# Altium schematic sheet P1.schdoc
size 297 x 209 mm; Symbol: Drawing-Symbol_A4; @Project Name: fmcw; @Page Count: 1; @Update Date: 2026-07-30; @Create Date: 2026-07-30; @Schematic Name: Schematic2; @Page No: 1; @Page Name: P1; Company: EasyEDA.com; Version: V1.0; Page Size: A4; Device: Drawing-Symbol_A4; @Create Time: 16:14:03; @Update Time: 16:14:03; Border: 1; Width: 1170; Height: 825; Region Start: 1; X Region Count: 6; Y Region Count: 4; Blade Width: 10; Title Block Position: 3; @Board Name: PCB2
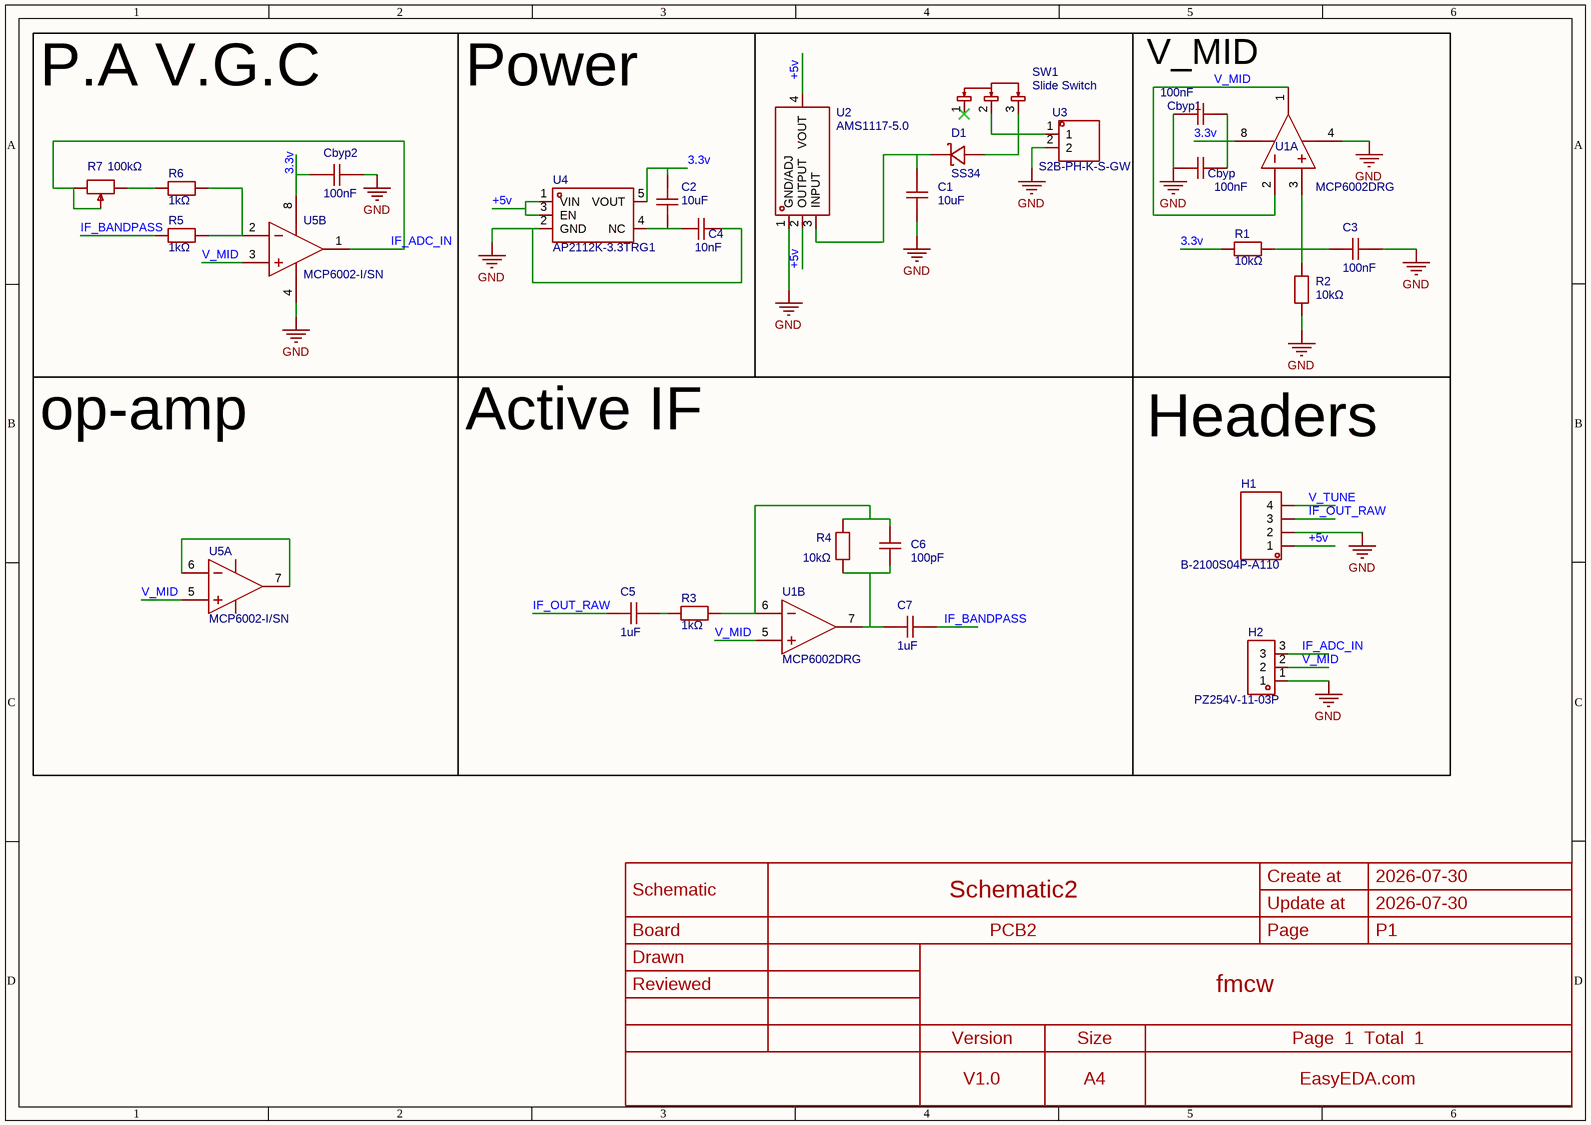
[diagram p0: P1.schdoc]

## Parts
C1  10uF  [C0603]
C2  10uF  [C0603]
C3  100nF  [C0402]
C4  10nF  [C0402]
C5  1uF  [C0402]
C6  100pF  [C0603]
C7  1uF  [C0402]
Cbyp  100nF  [C0402]
Cbyp1  100nF  [C0402]
Cbyp2  100nF  [C0402]
D1  SS34  [SMA_L4.3-W2.6-LS5.2-RD]
H1  B-2100S04P-A110  [HDR-TH_4P-P2.54-V-M]
H2  PZ254V-11-03P  [HDR-TH_3P-P2.54-V-M_PZ254V-11-03P]
R1  10kΩ  [R0402]
R2  10kΩ  [R0402]
R3  1kΩ  [R0402]
R4  10kΩ  [R0402]
R5  1kΩ  [R0402]
R6  1kΩ  [R0402]
R7  100kΩ  [RES-ADJ-TH_3296W]
SW1  Slide Switch  [SW-SMD_MST-12D18G4-SPDT-SLIDE-SWITCH]
U1  MCP6002DRG  [SOP-8_L4.9-W3.9-P1.27-LS6.0-BL]  (parts A,B of 2)
U2  AMS1117-5.0  [SOT-223-3_L6.5-W3.4-P2.30-LS7.0-BR]
U3  S2B-PH-K-S-GW  [CONN-TH_S2B-PH-K-S-GW]
U4  AP2112K-3.3TRG1  [SOT-23-5_L2.9-W1.6-P0.95-LS2.8-BR]
U5  MCP6002-I/SN  [SOIC-8_L4.9-W3.9-P1.27-LS6.0-BL]  (parts A,B of 2)

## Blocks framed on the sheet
P.A V.G.C: Cbyp2 R5-R7 U5
Power: C1-C4 Cbyp Cbyp1 D1 R1 R2 SW1 U1-U4
op-amp: U5
Active IF: C5-C7 R3 R4 U1
Headers: H1 H2

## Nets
GND: C1.1 C3.2 C4.2 Cbyp.2 Cbyp1.2 Cbyp2.2 H1.2 H2.1 R2.1 U1.4(VSS) U2.1(GND/ADJ) U3.2 U4.2(GND) U5.4(VSS)
3.3v: C2.1 Cbyp.1 Cbyp1.1 Cbyp2.1 R1.1 U1.8(VDD) U4.5(VOUT) U5.8(VDD)
+5v: H1.1 U2.2(OUTPUT) U2.4(VOUT) U4.1(VIN) U4.3(EN)
IF_ADC_IN: H2.3 R7.1 R7.2 U5.1(VOUTA)
IF_BANDPASS: C7.1 R5.1
IF_OUT_RAW: C5.2 H1.3
V_MID: H2.2 U1.1(OUTA) U1.2(INA-) U1.5(INB+) U5.3(VINA+) U5.5(VINB+)
V_TUNE: H1.4
NetC1_2: C1.2 D1.1(K) U2.3(INPUT)
NetC2_2: C2.2 C4.1 U4.4(NC)
NetC3_1: C3.1 R1.2 R2.2 U1.3(INA+)
NetC5_1: C5.1 R3.1
NetC6_1: C6.1 C7.2 R4.2 U1.7(OUTB)
NetC6_2: C6.2 R3.2 R4.1 U1.6(INB-)
NetD1_2: D1.2(A) SW1.3
NetR5_2: R5.2 R6.2 U5.2(VINA-)
NetR6_1: R6.1 R7.3
NetSW1_2: SW1.2 U3.1
NetU5_6: U5.6(VINB-) U5.7(VOUTB)

Not connected (* = marked no-connect by the designer): SW1 1*

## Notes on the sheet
- V_MID

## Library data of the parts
C1 C2 = CL10A106KP8NNNC: Capacitance:10uF Tolerance:±10% Tolerance:±10% Voltage Rating:10V Temperature Coefficient:X5R; Manufacturer: SAMSUNG(三星); AddInBom: yes; ModelId: 624118aa3cc7497086c383c2d72e08520819f05c4eef4c71ace90d822a990e87; ModelName: C0603_L1.6-W0.8-H0.8; ModelTransform: 62.992,31.496,0,0,0,0,0,0,0; Tolerance: ±10%; Voltage Rating: 10V; Temperature Coefficient: X5R
C3 = CL05B104KO5NNNC: Capacitance:100nF Tolerance:±10% Tolerance:±10% Voltage Rating:16V Temperature Coefficient:X7R; Manufacturer: SAMSUNG(三星); AddInBom: yes; ModelId: b7d13df3e9464d7a99d0651d1a5b4d570819f05c4eef4c71ace90d822a990e87; ModelName: C0402_L1.0-W0.5-H0.5; ModelTransform: 39.37,19.685,0,0,0,0,0,0,0; Tolerance: ±10%; Voltage Rating: 16V; Temperature Coefficient: X7R
C4 = CL05B103KB5NNNC: Capacitance:10nF Tolerance:±10% Tolerance:±10% Voltage Rating:50V Temperature Coefficient:X7R; Manufacturer: SAMSUNG(三星); AddInBom: yes; ModelId: b7d13df3e9464d7a99d0651d1a5b4d570819f05c4eef4c71ace90d822a990e87; ModelName: C0402_L1.0-W0.5-H0.5; ModelTransform: 39.37,19.685,0,0,0,0,0,0,0; Tolerance: ±10%; Voltage Rating: 50V; Temperature Coefficient: X7R
C5 C7 = TCC0402X5R105M6R3AT: Capacitance:1uF Tolerance:±20% Tolerance:±20% Voltage Rating:6.3V Temperature Coefficient:X5R; Manufacturer: CCTC(三环); 3D Model: b7d13df3e9464d7a99d0651d1a5b4d570819f05c4eef4c71ace90d822a990e87; 3D Model Transform: 39.37,19.685,0,0,0,0,0,0,0; Tolerance: ±20%; Voltage Rating: 6.3V; Temperature Coefficient: X5R; AddInBom: yes; ModelName: C0402_L1.0-W0.5-H0.5
C6 = CL10C101JB8NNNC: Capacitance:100pF Tolerance:±5% Tolerance:±5% Voltage Rating:50V Temperature Coefficient:C0G; Manufacturer: SAMSUNG(三星); AddInBom: yes; ModelId: 624118aa3cc7497086c383c2d72e08520819f05c4eef4c71ace90d822a990e87; ModelName: C0603_L1.6-W0.8-H0.8; ModelTransform: 62.992,31.496,0,0,0,0,0,0,0; Tolerance: ±5%; Voltage Rating: 50V; Temperature Coefficient: C0G
Cbyp Cbyp1 Cbyp2 = CL05B104KO5NNNC: Capacitance:100nF Tolerance:±10% Tolerance:±10% Voltage Rating:16V Temperature Coefficient:X7R; Manufacturer: SAMSUNG(三星); 3D Model: b7d13df3e9464d7a99d0651d1a5b4d570819f05c4eef4c71ace90d822a990e87; 3D Model Transform: 39.37,19.685,0,0,0,0,0,0,0; Tolerance: ±10%; Voltage Rating: 16V; Temperature Coefficient: X7R; AddInBom: yes; ModelName: C0402_L1.0-W0.5-H0.5
D1 = SS34_C8678: Diode Configuration:Independent Voltage - Forward(Vf@If):550mV@3A Voltage - DC Reverse(Vr):40V Current - Rectified:3A Reverse Leakage Current (Ir):500uA@40V Operating Junction Temperature Range:-55℃~+125℃ Operating Junction Temperature Range:-55℃~+125℃; Manufacturer: MDD(辰达半导体); AddInBom: yes; ModelId: e3551acb3c5a4975a5e9d36087fe1fa20819f05c4eef4c71ace90d822a990e87; ModelTransform: 185.039,102.362,0,0,0,0,0,0,0; Voltage - DC Reverse(Vr): 40V; Current - Rectified: 3A
H1 = B-2100S04P-A110: Pin Structure:1x4P Pitch:2.54mm Row Spacing:- Circluar Pins/Square Pins:Pin Header Mounting Type:Through Hole Number of Rows:1 Number of Pins:4P Current Rating:3A Voltage Rating (Max):- Length of Mating Pin:6mm Insulation Height:2.54mm Length of End Conne; Manufacturer: Ckmtw(灿科盟); Symbol: Header-Male-2.54_1x4; AddInBom: yes; ModelId: 69e0934d9b9245f6ab499bc5a319b3aa0819f05c4eef4c71ace90d822a990e87; ModelName: HDR-TH_4P-P2.54-M-LI-1X4P; ModelTransform: 399.999,104.7242,0,0,0,0,0,0,-118.11; Pin Structure: 1x4P; Pitch: 2.54mm; Current Rating: 3A
H2 = PZ254V-11-03P: Pin Structure:1x3P Pitch:2.54mm Row Spacing:- Circluar Pins/Square Pins:Pin Header Mounting Type:Through Hole Number of Rows:1 Number of Pins:3P Current Rating:3A Voltage Rating (Max):250V Length of Mating Pin:6mm Insulation Height:2.5mm Length of End Con; Manufacturer: XFCN(兴飞); Symbol: PZ254V-11-03P_C2937625; AddInBom: yes; ModelId: bd28a638fbd247be9398fd5d39c366ec0819f05c4eef4c71ace90d822a990e87; ModelTransform: 300.3931,100,0,0,0,0,0,0,-118.11; Pin Structure: 1x3P; Pitch: 2.54mm; Current Rating: 3A; Voltage Rating (Max): 250V
R1 R2 = FRC0402F1002TS: Type:Thick Film Resistor Resistance:10kΩ Tolerance:±1% Tolerance:±1% Power(Watts):62.5mW Voltage-Supply(Max):50V Temperature Coefficient:±100ppm/℃ Temperature Coefficient:±100ppm/℃ Operating Temperature:-55℃~+155℃ Operating Temperature:-55℃~+155℃; Manufacturer: FOJAN(富捷); AddInBom: yes; ModelId: efdecb7dae4442949d28eecaf748420f0819f05c4eef4c71ace90d822a990e87; ModelName: R0402_L1.0-W0.5-H0.4; ModelTransform: 39.37,19.685,0,0,0,0,0,0,0; Tolerance: ±1%; Power(Watts): 62.5mW; Voltage-Supply(Max): 50V
R3 R5 R6 = FRC0402J102 TS: Type:Thick Film Resistor Resistance:1kΩ Tolerance:±5% Tolerance:±5% Power(Watts):62.5mW Voltage-Supply(Max):50V Temperature Coefficient:±100ppm/℃ Temperature Coefficient:±100ppm/℃ Operating Temperature:-55℃~+155℃ Operating Temperature:-55℃~+155℃; Manufacturer: FOJAN(富捷); 3D Model: efdecb7dae4442949d28eecaf748420f0819f05c4eef4c71ace90d822a990e87; 3D Model Transform: 39.37,19.685,0,0,0,0,0,0,0; Tolerance: ±5%; Power(Watts): 62.5mW; Voltage-Supply(Max): 50V; AddInBom: yes; ModelName: R0402_L1.0-W0.5-H0.4
R4 = FRC0402F1002TS: Type:Thick Film Resistor Resistance:10kΩ Tolerance:±1% Tolerance:±1% Power(Watts):62.5mW Voltage-Supply(Max):50V Temperature Coefficient:±100ppm/℃ Temperature Coefficient:±100ppm/℃ Operating Temperature:-55℃~+155℃ Operating Temperature:-55℃~+155℃; Manufacturer: FOJAN(富捷); 3D Model: efdecb7dae4442949d28eecaf748420f0819f05c4eef4c71ace90d822a990e87; 3D Model Transform: 39.37,19.685,0,0,0,0,0,0,0; Tolerance: ±1%; Power(Watts): 62.5mW; Voltage-Supply(Max): 50V; AddInBom: yes; ModelName: R0402_L1.0-W0.5-H0.4
R7 = 3296W-1-104LF: Resistance:100kΩ Tolerance:±10% Tolerance:±10% Power(Watts):500mW Temperature Coefficient:±100ppm/℃ Temperature Coefficient:±100ppm/℃ Number of Turns:; Manufacturer: BOURNS; AddInBom: yes; ModelId: d75c81813a0c4fc5896bd8a59ffd69dd0819f05c4eef4c71ace90d822a990e87; ModelTransform: 374.015,188.976,0,90,0,0,2.362,0.005,-137.795; Tolerance: ±10%; Power(Watts): 500mW
SW1 = MST-12D18G4 SPDT Slide Switch: Circuit:SPDT Actuator Style:Rectangular Columnar Termination Style:SMD(SMT) Tab Length:9.1mm Width:3.5mm Switch Height:7.5mm Mounting Type:Surface Mount, Right Angle Actuator Color:Black Current Rating:100mA Voltage Rating:12V Life:10,000 Cycles Operating; Manufacturer: SHOU HAN(首韩); AddInBom: yes; ModelId: 054f6ac983204f28b99156bbc43be73a0819f05c4eef4c71ace90d822a990e87; ModelTransform: 358.661,381.889,0,0,0,0,0,-161.417,-19.685; Circuit: SPDT; Switch Height: 7.5mm; Actuator Color: Black; Current Rating: 100mA; Voltage Rating: 12V
U1 = MCP6002DRG: Number of Channels:2 Maximum Power Supply Range (Vdd-Vss):7.5V Rail to Rail:Rail-to-Rail Input, Rail-to-Rail Output Gain Bandwidth Product:1MHz Vos - Input Offset Voltage:3.5mV Input Offset Voltage Drift(Vos TC):2.7uV/℃ Slew Rate:800V/ms Ib - Input Bias C; Manufacturer: HGC(深圳汉芯); Relevance: []; AddInBom: yes; ModelId: 9e479aa4755a4392b89c401224ad12750819f05c4eef4c71ace90d822a990e87; ModelName: SOP-8_L4.9-W3.9-P1.27-LS6.0-BL-1; ModelTransform: 192.913,236.22,0,0,0,0,-0.393,2.749,0; Number of Channels: 2; Maximum Power Supply Range (Vdd-Vss): 7.5V; Gain Bandwidth Product: 1MHz; Vos - Input Offset Voltage: 3.5mV; Ib - Input Bias Current: 1pA; Input Voltage Noise Density: 27nV/√Hz@1kHz; Common Mode Rejection Ratio(CMRR): 70dB; Quiescent Current: 75uA; Output Current: 84mA; Single supply: 1.8V~6V
U2 = AMS1117-5.0_C18212701: Output Type:Fixed Voltage - Supply:12V Output Voltage:5V Output Voltage:5V Output Current:1A Power Supply Rejection Ratio (PSRR):- Voltage Dropout:1.3V@(1A) standby current:4mA Noise:- Features:Over Current Protection；Thermal Shutdown Operating Temperatur; Manufacturer: TECH PUBLIC(台舟); AddInBom: yes; ModelId: e5f8b32b785646b6abbef6d5ae2fe0600819f05c4eef4c71ace90d822a990e87; ModelName: SOT-223-4P_L6.5-W3.5-H1.6-LS7.0-P2.30; ModelTransform: 279.89794,255.905,0,180,0,0,-3.9385,-0.0005,0; Output Type: Fixed; Voltage - Supply: 12V; Output Voltage: 5V; standby current: 4mA; Output Configuration: Positive; Number of Outputs: 1
U3 = S2B-PH-K-S-GW: Pins Structure:1x2P Pitch:2mm Mounting Type:Right Angle Reference Series:PH Number of Pins:2P Number of Rows:1 Number of PINs Per Row:2 Row Spacing:- Current Rating:2A Contact Material:Brass Contact Plating:Tin Operating Temperature:-25℃~+85℃ Operating Te; Manufacturer: JST; AddInBom: yes; ModelId: 1dc56e0a126b488da226fc64d36e59340819f05c4eef4c71ace90d822a990e87; ModelTransform: 232.283,299.212,0,0,0,0,0,97.047,-133.858; Pins Structure: 1x2P; Pitch: 2mm; Reference Series: PH; Number of PINs Per Row: 2; Current Rating: 2A; Voltage Rating: 100V; Plastic Material: PA66; Flame Retardant Rating: UL94V-0; Supplementary Features: K Pin; Z-Height of the Board: 4.8mm; X-Length of Bottom Edge on Board (Spacing Line): 5.9mm; Y-Width of Bottom Edge on Board: 7.6mm
U4 = AP2112K-3.3TRG1_C23380830: Output Configuration:Positive Voltage - Supply:5.5V Output Voltage:3.3V Output Voltage:3.3V Output Current:600mA Power Supply Rejection Ratio (PSRR):75dB@(1kHz) Voltage Dropout:320mV@(600mA) standby current:10uA Noise:- Features:Enable control；Over Curren; Manufacturer: TECH PUBLIC(台舟); AddInBom: yes; ModelId: 5bf53fa97d9848eeb37d584d4730b7f10819f05c4eef4c71ace90d822a990e87; ModelTransform: 114.173,114.173,0,90,0,0,0,0,0; Voltage - Supply: 5.5V; Output Voltage: 3.3V; standby current: 10uA; Output Type: Fixed; Number of Outputs: 1
U5 = MCP6002-I/SN: Number of Channels:2 Maximum Power Supply Range (Vdd-Vss):5.5V Rail to Rail:Rail-to-Rail Input, Rail-to-Rail Output Gain Bandwidth Product:1MHz Vos - Input Offset Voltage:4.5mV Input Offset Voltage Drift(Vos TC):2uV/℃ Slew Rate:600V/ms Ib - Input Bias Cur; Manufacturer: MICROCHIP(美国微芯); Relevance: []; AddInBom: yes; ModelId: 2ec1ac1bf9bf4d09a988fcee15e6a02d0819f05c4eef4c71ace90d822a990e87; ModelName: SOIC-8_L4.9-W3.9-H1.7-LS6.0-P1.27; ModelTransform: 192.913,236.22,0,0,0,0,0,0,0; Number of Channels: 2; Maximum Power Supply Range (Vdd-Vss): 5.5V; Gain Bandwidth Product: 1MHz; Vos - Input Offset Voltage: 4.5mV; Input Offset Voltage Drift(Vos TC): 2uV/℃; Ib - Input Bias Current: 1pA; Input Voltage Noise Density: 28nV/√Hz@1kHz; Common Mode Rejection Ratio(CMRR): 76dB; Quiescent Current: 100uA; Output Current: 23mA; Single supply: 1.8V~5.5V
